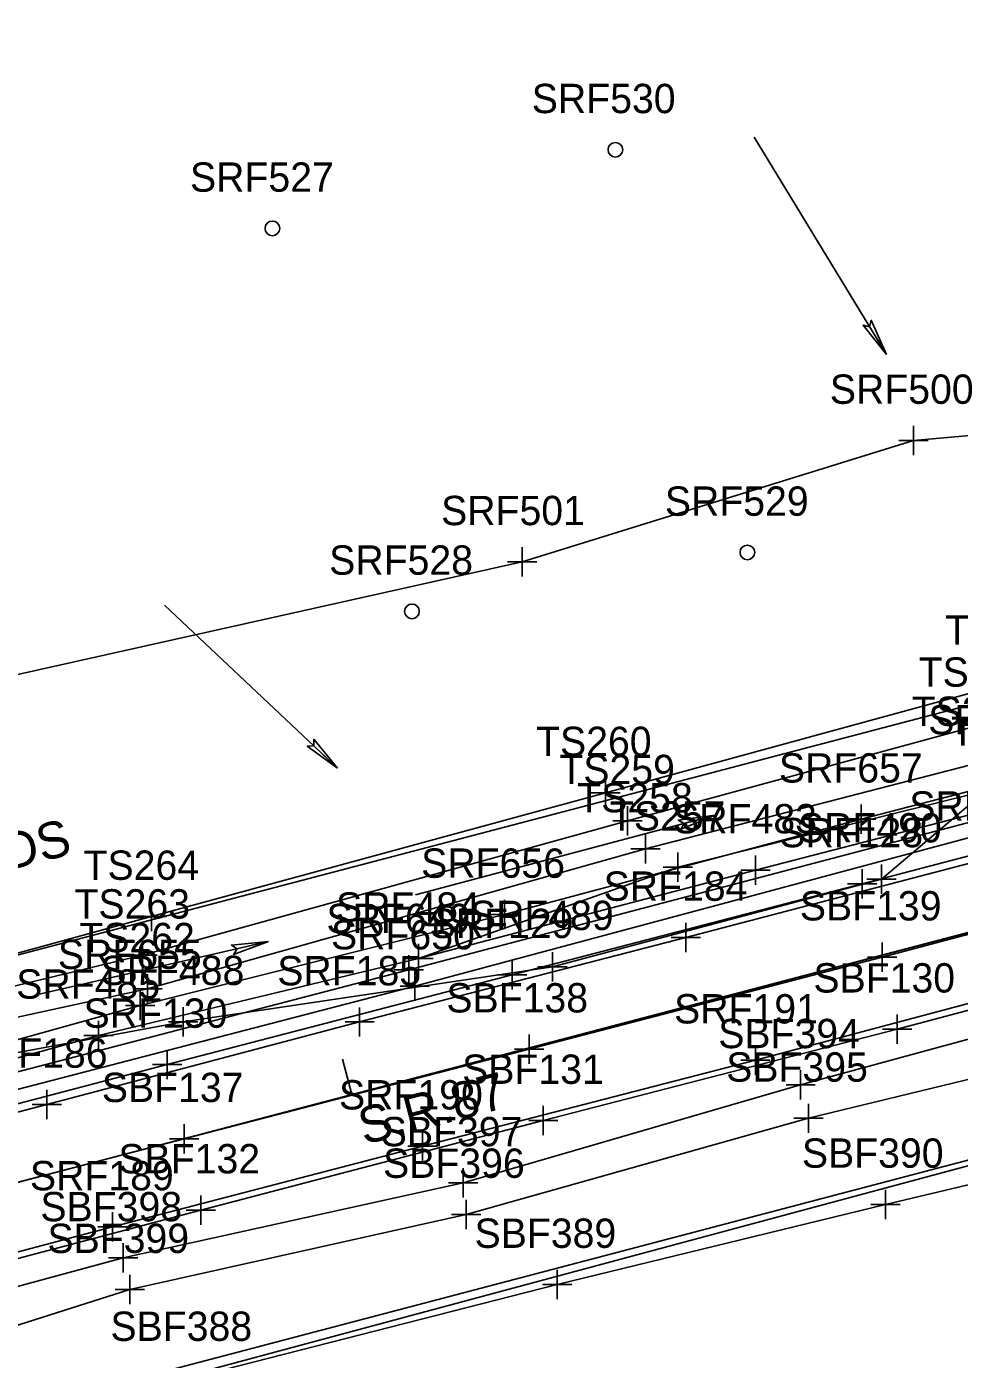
# Model space of a CAD drawing. Extents: x 818717 to 846077, y 440014 to 541392.
# Drawn here: x 831206.2 to 831333.4, y 492949.3 to 493131.1 of the extents above; entities that cross this region are included whole.
import ezdxf

# ---------------------------------------------------------------- set-up
doc = ezdxf.new("R2010")
doc.units = 0
for name, color, linetype in [('SURVEY - CENTERLINE - Preliminary', 7, 'Continuous'), ('SURVEY - CENTERLINE - Preliminary Text', 7, 'Continuous'), ('SURVEY - DRAINAGE - Area Shapes', 7, 'Continuous'), ('SURVEY - DRAINAGE - Natural Features Text', 7, 'Continuous'), ('SURVEY - DTM - Breaklines', 7, 'Continuous'), ('SURVEY - DTM - Breaklines - Points - Locators', 7, 'Continuous'), ('SURVEY - DTM - Breaklines - Points - Numbers', 7, 'Continuous'), ('SURVEY - DTM - Spot Points - Locators', 7, 'Continuous'), ('SURVEY - DTM - Spot Points - Point Numbers', 7, 'Continuous'), ('SURVEY - PROPERTY - ROW Lines', 7, 'Continuous'), ('SURVEY - TRAFFIC CONTROL - Pavement Marking - Points - Locators', 7, 'Continuous'), ('SURVEY - TRAFFIC CONTROL - Pavement Marking - Points - Numbers', 7, 'Continuous'), ('SURVEY - TRAFFIC CONTROL - Pavement Marking with Text', 7, 'Continuous'), ('SURVEY - TRANSPORTATION - Roads', 7, 'Continuous'), ('SURVEY - TRANSPORTATION - Roads - Points - Locators', 7, 'Continuous'), ('SURVEY - TRANSPORTATION - Roads - Points - Numbers', 7, 'Continuous'), ('SURVEY - TRANSPORTATION - Roads Text', 7, 'Continuous'), ('SURVEY - UTILITIES - Electric (Overhead) with Text', 7, 'Continuous'), ('SURVEY - UTILITIES - Telephone (Underground) - Points - Locators', 7, 'Continuous'), ('SURVEY - UTILITIES - Telephone (Underground) - Points - Numbers', 7, 'Continuous'), ('SURVEY - UTILITIES - Telephone (Underground) with Text', 7, 'Continuous'), ('SURVEY - UTILITIES - Water - Points - Locators', 7, 'Continuous'), ('SURVEY - UTILITIES - Water - Points - Numbers', 7, 'Continuous'), ('SURVEY - UTILITIES - Water with Text', 7, 'Continuous'), ('SURVEY - VEGETATION - Features - Points - Locators', 7, 'Continuous'), ('SURVEY - VEGETATION - Features - Points - Numbers', 7, 'Continuous'), ('SURVEY - VEGETATION - Features with Text', 7, 'Continuous')]:
    doc.layers.add(name, color=color, linetype=linetype)

msp = doc.modelspace()

# ---------------------------------------------------------------- linework, layer by layer
at = {"layer": 'SURVEY - CENTERLINE - Preliminary'}
msp.add_line((830960.37, 492909.24), (831419.96, 493029.94), dxfattribs=at)
msp.add_line((830960.37, 492909.24), (831419.96, 493029.94), dxfattribs=at)
msp.add_line((830960.37, 492909.24), (831419.96, 493029.94), dxfattribs=at)
at = {"layer": 'SURVEY - CENTERLINE - Preliminary Text'}
msp.add_line((831250.53, 492985.45), (831249.26, 492990.28), dxfattribs=at)
at = {"layer": 'SURVEY - DRAINAGE - Area Shapes'}
msp.add_lwpolyline([(833331.86, 493535.43), (832825.85, 493400.54), (832121.68, 493216.64), (831495.16, 493049.75), (830960.37, 492909.24), (830124.73, 492686.08), (830069.9, 493396.23), (830870.86, 494031.84), (831248.11, 494413.67), (831536.95, 494545.33), (832050.07, 494534.01), (832097.96, 494614.84), (832139.36, 494784.62), (832167.46, 494840.58), (832274.31, 494844.36), (832647.22, 494804.13), (832934.24, 494910.41), (833081.03, 494456.05), (833331.86, 493535.43)], dxfattribs=at)
at = {"layer": 'SURVEY - DRAINAGE - Natural Features Text'}
for p, q in [((831323.47, 493086.43), (831305.44, 493116.04)), ((831322.06, 493088.74), (831323.47, 493086.43)), ((831248.57, 493029.99), (831224.99, 493052.2)), ((831246.6, 493031.84), (831248.57, 493029.99)), ((831300.12, 493023.57), (831259.21, 493012.69)), ((831297.51, 493022.88), (831300.12, 493023.57)), ((831239.18, 493006.35), (831207.27, 492999.01)), ((831236.55, 493005.74), (831239.18, 493006.35))]:
    msp.add_line(p, q, dxfattribs=at)
for points in [[(831323.47, 493086.43), (831320.29, 493090.4), (831321.18, 493090.19), (831321.4, 493091.08)], [(831248.57, 493029.99), (831244.45, 493032.98), (831245.37, 493033.01), (831245.34, 493033.92)], [(831300.12, 493023.57), (831295.41, 493021.64), (831295.87, 493022.44), (831295.07, 493022.9)], [(831239.18, 493006.35), (831234.41, 493004.58), (831234.9, 493005.36), (831234.12, 493005.85)]]:
    msp.add_lwpolyline(points, close=True, dxfattribs=at)
for points in [[(831323.47, 493086.43), (831320.29, 493090.4), (831321.18, 493090.19), (831321.4, 493091.08), (831323.47, 493086.43)], [(831248.57, 493029.99), (831244.45, 493032.98), (831245.37, 493033.01), (831245.34, 493033.92), (831248.57, 493029.99)], [(831300.12, 493023.57), (831295.41, 493021.64), (831295.87, 493022.44), (831295.07, 493022.9), (831300.12, 493023.57)], [(831239.18, 493006.35), (831234.41, 493004.58), (831234.9, 493005.36), (831234.12, 493005.85), (831239.18, 493006.35)]]:
    msp.add_lwpolyline(points, dxfattribs=at)
at = {"layer": 'SURVEY - DTM - Breaklines'}
for points in [[(831172.33, 492965.05), (831181.59, 492967.43), (831227.67, 492979.44), (831274.72, 492991.66), (831322.92, 493004.21), (831368.33, 493016.26), (831413.81, 493028.29), (831465.87, 493041.9), (831511.63, 493053.91), (831556.79, 493065.9), (831604.84, 493079.03), (831650.91, 493091.16), (831699.1, 493103.99), (831742.48, 493115.71)], [(831532.14, 493094.44), (831486.29, 493082.49), (831415.63, 493063.89), (831383.16, 493053.36), (831340.91, 493041.84), (831285.15, 493026.64), (831223.23, 493009.75), (831163.61, 492993.48)], [(831533.39, 493093.08), (831489.03, 493078.67), (831431.59, 493059.14), (831388.21, 493049.94), (831337.17, 493036.1), (831288.16, 493022.81), (831221.99, 493004.47), (831163.9, 492990.46)], [(831535.36, 493091.17), (831488.68, 493075.37), (831432.58, 493055.29), (831391.04, 493045.72), (831336.22, 493030.75), (831290.63, 493018.96), (831222.65, 492999.88), (831164.87, 492987.27)], [(831537.69, 493087.97), (831489.3, 493071.65), (831438.65, 493053.39), (831396.75, 493041.74), (831341.58, 493028.03), (831295.03, 493016.46), (831259.62, 493004.04)], [(831550.6, 493086.08), (831528.73, 493075.33), (831482.27, 493062.41), (831435.51, 493050.33), (831391.53, 493037.77), (831349.43, 493027.4), (831305.62, 493016.09), (831259.62, 493004.04), (831215.99, 492993.54), (831167.49, 492980.12)], [(831371.1, 493001.48), (831357.72, 492999.27), (831311.78, 492986.79), (831265.73, 492973.41), (831219.33, 492963.18), (831175.85, 492951.43)], [(831358.62, 492993.34), (831312.86, 492982.22), (831266.15, 492969.1), (831220.27, 492958.85), (831177.33, 492945.24)], [(831183.26, 492932.89), (831228.9, 492946.86), (831278.55, 492959.55), (831323.37, 492970.48), (831362.8, 492979.81)]]:
    msp.add_lwpolyline(points, dxfattribs=at)
at = {"layer": 'SURVEY - DTM - Breaklines - Points - Locators'}
for p, q in [((831285.15, 493028.64), (831285.15, 493024.64)), ((831287.15, 493026.64), (831283.15, 493026.64)), ((831288.16, 493024.81), (831288.16, 493020.81)), ((831290.16, 493022.81), (831286.16, 493022.81)), ((831290.63, 493020.96), (831290.63, 493016.96)), ((831292.63, 493018.96), (831288.63, 493018.96)), ((831295.03, 493018.46), (831295.03, 493014.46)), ((831305.62, 493018.09), (831305.62, 493014.09)), ((831297.03, 493016.46), (831293.03, 493016.46)), ((831307.62, 493016.09), (831303.62, 493016.09)), ((831223.23, 493011.75), (831223.23, 493007.75)), ((831225.23, 493009.75), (831221.23, 493009.75)), ((831221.99, 493006.47), (831221.99, 493002.47)), ((831259.62, 493006.04), (831259.62, 493002.04)), ((831322.92, 493006.21), (831322.92, 493002.21)), ((831223.99, 493004.47), (831219.99, 493004.47)), ((831261.62, 493004.04), (831257.62, 493004.04)), ((831324.92, 493004.21), (831320.92, 493004.21)), ((831222.65, 493001.88), (831222.65, 492997.88)), ((831224.65, 492999.88), (831220.65, 492999.88)), ((831215.99, 492995.54), (831215.99, 492991.54)), ((831217.99, 492993.54), (831213.99, 492993.54)), ((831274.72, 492993.66), (831274.72, 492989.66)), ((831276.72, 492991.66), (831272.72, 492991.66)), ((831311.78, 492988.79), (831311.78, 492984.79)), ((831313.78, 492986.79), (831309.78, 492986.79)), ((831312.86, 492984.22), (831312.86, 492980.22)), ((831314.86, 492982.22), (831310.86, 492982.22)), ((831227.67, 492981.44), (831227.67, 492977.44)), ((831229.67, 492979.44), (831225.67, 492979.44)), ((831265.73, 492975.41), (831265.73, 492971.41)), ((831267.73, 492973.41), (831263.73, 492973.41)), ((831323.37, 492972.48), (831323.37, 492968.48)), ((831266.15, 492971.1), (831266.15, 492967.1)), ((831268.15, 492969.1), (831264.15, 492969.1)), ((831325.37, 492970.48), (831321.37, 492970.48)), ((831219.33, 492965.18), (831219.33, 492961.18)), ((831221.33, 492963.18), (831217.33, 492963.18)), ((831278.55, 492961.55), (831278.55, 492957.55)), ((831220.27, 492960.85), (831220.27, 492956.85)), ((831222.27, 492958.85), (831218.27, 492958.85)), ((831280.55, 492959.55), (831276.55, 492959.55))]:
    msp.add_line(p, q, dxfattribs=at)
at = {"layer": 'SURVEY - DTM - Spot Points - Locators'}
for centre in [(831286.5, 493114.33), (831239.7, 493103.61), (831304.51, 493059.41), (831258.74, 493051.37)]:
    msp.add_circle(centre, 1, dxfattribs=at)
at = {"layer": 'SURVEY - PROPERTY - ROW Lines'}
for p, q in [((831412.34, 493058.96), (830952.75, 492938.26)), ((830967.99, 492880.22), (831427.58, 493000.93))]:
    msp.add_line(p, q, dxfattribs=at)
at = {"layer": 'SURVEY - TRAFFIC CONTROL - Pavement Marking - Points - Locators'}
for p, q in [((831296.13, 493008.89), (831296.13, 493004.89)), ((831298.13, 493006.89), (831294.13, 493006.89)), ((831251.61, 492997.36), (831251.61, 492993.36)), ((831253.61, 492995.36), (831249.61, 492995.36)), ((831305.6, 492992.16), (831305.6, 492988.16)), ((831307.6, 492990.16), (831303.6, 492990.16)), ((831208.94, 492986.12), (831208.94, 492982.12)), ((831210.94, 492984.12), (831206.94, 492984.12)), ((831260.2, 492980.43), (831260.2, 492976.43)), ((831262.2, 492978.43), (831258.2, 492978.43)), ((831217.88, 492969.4), (831217.88, 492965.4)), ((831219.88, 492967.4), (831215.88, 492967.4))]:
    msp.add_line(p, q, dxfattribs=at)
at = {"layer": 'SURVEY - TRAFFIC CONTROL - Pavement Marking with Text'}
for points in [[(832159.39, 493235.77), (832116.7, 493224.52), (832072.63, 493213.17), (832030, 493201.97), (831987.46, 493190.83), (831936.58, 493177.36), (831894.1, 493165.96), (831849.46, 493153.92), (831808.03, 493142.52), (831768.36, 493131.66), (831727.87, 493120.89), (831684.5, 493109.18), (831641.68, 493097.86), (831599.16, 493086.58), (831554.58, 493074.61), (831511.86, 493063.5), (831467.07, 493051.66), (831425.05, 493040.69), (831380.34, 493029.11), (831337.84, 493017.82), (831296.13, 493006.89), (831251.61, 492995.36), (831208.94, 492984.12), (831169.87, 492973.88)], [(831174.64, 492955.97), (831217.88, 492967.4), (831260.2, 492978.43), (831305.6, 492990.16), (831350.87, 493002.2), (831397.34, 493014.25), (831441.59, 493025.83), (831487.77, 493037.91), (831534.41, 493050.33), (831587.19, 493064.38), (831630.52, 493075.92), (831676.82, 493088.3), (831723.86, 493100.96), (831758.43, 493110.25), (831806.28, 493123.18), (831848.98, 493134.67), (831896.65, 493147.52), (831940.52, 493159.26), (831989.17, 493172.11), (832037.06, 493184.69), (832086.82, 493197.77), (832134.83, 493210.3)]]:
    msp.add_lwpolyline(points, dxfattribs=at)
at = {"layer": 'SURVEY - TRANSPORTATION - Roads'}
for points in [[(831740.14, 493125.18), (831693.82, 493112.89), (831648.31, 493100.78), (831602.5, 493088.65), (831573.14, 493081.02), (831536.49, 493071.33), (831509.09, 493063.99), (831462.95, 493051.69), (831417.27, 493039.63), (831365.78, 493026.17), (831320.15, 493014.2), (831272.42, 493001.81), (831225.35, 492989.57), (831179.26, 492977.48), (831169.53, 492974.82)], [(831745.28, 493105.9), (831698.71, 493093.56), (831652.79, 493081.06), (831606.96, 493068.69), (831560.39, 493056.4), (831514.16, 493044.16), (831468.16, 493032.15), (831422.28, 493020.03), (831370.82, 493006.55), (831324.94, 492994.38), (831276.67, 492981.92), (831229.94, 492969.71), (831184.11, 492957.61), (831175.07, 492955.18)]]:
    msp.add_lwpolyline(points, dxfattribs=at)
at = {"layer": 'SURVEY - TRANSPORTATION - Roads - Points - Locators'}
for p, q in [((831320.15, 493016.2), (831320.15, 493012.2)), ((831322.15, 493014.2), (831318.15, 493014.2)), ((831272.42, 493003.81), (831272.42, 492999.81)), ((831274.42, 493001.81), (831270.42, 493001.81)), ((831324.94, 492996.38), (831324.94, 492992.38)), ((831326.94, 492994.38), (831322.94, 492994.38)), ((831225.35, 492991.57), (831225.35, 492987.57)), ((831227.35, 492989.57), (831223.35, 492989.57)), ((831276.67, 492983.92), (831276.67, 492979.92)), ((831278.67, 492981.92), (831274.67, 492981.92)), ((831229.94, 492971.71), (831229.94, 492967.71)), ((831231.94, 492969.71), (831227.94, 492969.71))]:
    msp.add_line(p, q, dxfattribs=at)
at = {"layer": 'SURVEY - UTILITIES - Electric (Overhead) with Text'}
msp.add_lwpolyline([(832667.18, 493331.74), (832415.28, 493266.23), (832147.85, 493195.27), (831907.96, 493131.64), (831666.03, 493064.14), (831375.19, 492986.65), (831101.3, 492913.04)], dxfattribs=at)
at = {"layer": 'SURVEY - UTILITIES - Telephone (Underground) - Points - Locators'}
for p, q in [((831258.34, 493004.49), (831258.34, 493000.49)), ((831260.34, 493002.49), (831256.34, 493002.49)), ((831259.12, 493002.26), (831259.12, 492998.26)), ((831261.12, 493000.26), (831257.12, 493000.26))]:
    msp.add_line(p, q, dxfattribs=at)
at = {"layer": 'SURVEY - UTILITIES - Telephone (Underground) with Text'}
for points in [[(831168.45, 492979.07), (831258.34, 493002.49), (831351.65, 493027.04)], [(831169.15, 492976.87), (831259.12, 493000.26), (831352.34, 493025.2)]]:
    msp.add_lwpolyline(points, dxfattribs=at)
at = {"layer": 'SURVEY - UTILITIES - Water - Points - Locators'}
for p, q in [((831320.05, 493025.02), (831320.05, 493021.02)), ((831322.05, 493023.02), (831318.05, 493023.02)), ((831271.35, 493012.03), (831271.35, 493008.03)), ((831273.35, 493010.03), (831269.35, 493010.03)), ((831221.68, 492999.59), (831221.68, 492995.59)), ((831223.68, 492997.59), (831219.68, 492997.59))]:
    msp.add_line(p, q, dxfattribs=at)
at = {"layer": 'SURVEY - UTILITIES - Water with Text'}
msp.add_lwpolyline([(831168.53, 492982.83), (831221.68, 492997.59), (831271.35, 493010.03), (831320.05, 493023.02), (831382.11, 493039.09), (831464.43, 493059.02), (831521.6, 493075.98), (831637.27, 493105.47), (831699.54, 493130.69), (831734.63, 493142.29), (831763.92, 493149.4), (831800.53, 493157.83), (831844.47, 493169.57), (831878.73, 493177.18), (831933.72, 493193.59), (832000.95, 493211.25), (832058.59, 493225.48), (832113.6, 493238.29), (832172.68, 493261.93), (832217.98, 493273.66), (832269.17, 493287.2), (832330.79, 493299.45)], dxfattribs=at)
at = {"layer": 'SURVEY - VEGETATION - Features - Points - Locators'}
for p, q in [((831327.18, 493076.68), (831327.18, 493072.68)), ((831329.18, 493074.68), (831325.18, 493074.68)), ((831273.8, 493060.13), (831273.8, 493056.13)), ((831275.8, 493058.13), (831271.8, 493058.13)), ((831322.83, 493016.85), (831322.83, 493012.85)), ((831324.83, 493014.85), (831320.83, 493014.85)), ((831277.91, 493004.9), (831277.91, 493000.9)), ((831279.91, 493002.9), (831275.91, 493002.9)), ((831227.54, 492997.4), (831227.54, 492993.4)), ((831229.54, 492995.4), (831225.54, 492995.4))]:
    msp.add_line(p, q, dxfattribs=at)
at = {"layer": 'SURVEY - VEGETATION - Features with Text'}
msp.add_lwpolyline([(831133.17, 493025.25), (831188.61, 493039.11), (831273.8, 493058.13), (831327.18, 493074.68), (831372.45, 493078.69), (831446.52, 493103.4), (831511.7, 493128.91), (831543.94, 493118.92), (831551.05, 493086.4), (831538.72, 493077.69), (831488.18, 493059.71), (831414.15, 493041.53), (831340.28, 493029.6), (831322.83, 493014.85), (831277.91, 493002.9), (831227.54, 492995.4), (831165.97, 492983.97)], dxfattribs=at)

# ---------------------------------------------------------------- texts
at = {"layer": 'SURVEY - DTM - Breaklines - Points - Numbers'}
for s, p in [('TS256', (831331.51, 493046.84)), ('TS255', (831327.88, 493041.1)), ('TS254', (831326.93, 493035.75)), ('TS253', (831332.29, 493033.03)), ('TS260', (831275.68, 493031.64)), ('TS259', (831278.86, 493027.81)), ('TS258', (831281.3, 493023.96)), ('TS257', (831285.75, 493021.46)), ('SRF483', (831294.38, 493021.09)), ('TS264', (831213.94, 493014.75)), ('TS263', (831212.7, 493009.47)), ('SRF484', (831248.38, 493009.04)), ('SBF139', (831311.67, 493009.21)), ('TS262', (831213.36, 493004.88)), ('SRF485', (831204.75, 492998.54)), ('SBF138', (831263.44, 492996.66)), ('SBF394', (831300.54, 492991.79)), ('SBF395', (831301.62, 492987.22)), ('SBF137', (831216.43, 492984.44)), ('SBF397', (831254.49, 492978.41)), ('SBF396', (831254.8, 492974.1)), ('SBF390', (831311.95, 492975.48)), ('SBF398', (831208.05, 492968.18)), ('SBF399', (831209.01, 492963.85)), ('SBF389', (831267.29, 492964.55)), ('SBF388', (831217.61, 492951.86))]:
    msp.add_text(s, height=4, dxfattribs=at).set_placement(p)
at = {"layer": 'SURVEY - DTM - Spot Points - Point Numbers'}
for s, p in [('SRF530', (831275.09, 493119.33)), ('SRF527', (831228.46, 493108.61)), ('SRF529', (831293.25, 493064.41)), ('SRF528', (831247.45, 493056.37))]:
    msp.add_text(s, height=4, dxfattribs=at).set_placement(p)
at = {"layer": 'SURVEY - TRAFFIC CONTROL - Pavement Marking - Points - Numbers'}
for s, p in [('SRF183', (831326.6, 493022.82)), ('SRF184', (831284.89, 493011.89)), ('SRF185', (831240.37, 493000.36)), ('SRF191', (831294.51, 492995.16)), ('SRF186', (831197.59, 492989.12)), ('SRF190', (831248.79, 492983.43)), ('SRF189', (831206.62, 492972.4))]:
    msp.add_text(s, height=4, dxfattribs=at).set_placement(p)
at = {"layer": 'SURVEY - TRANSPORTATION - Roads - Points - Numbers'}
for s, p in [('SRF128', (831308.86, 493019.2)), ('SRF129', (831261.16, 493006.81)), ('SBF130', (831313.52, 492999.38)), ('SRF130', (831213.94, 492994.57)), ('SBF131', (831265.59, 492986.92)), ('SBF132', (831218.7, 492974.71))]:
    msp.add_text(s, height=4, dxfattribs=at).set_placement(p)
at = {"layer": 'SURVEY - TRANSPORTATION - Roads Text'}
msp.add_text('S.R.87', height=5, rotation=14.7154, dxfattribs=at).set_placement((831252.22, 492978.59))
at = {"layer": 'SURVEY - UTILITIES - Telephone (Underground) - Points - Numbers'}
for s, p in [('SRF649', (831247.08, 493007.49)), ('SRF650', (831247.7, 493005.26))]:
    msp.add_text(s, height=4, dxfattribs=at).set_placement(p)
at = {"layer": 'SURVEY - UTILITIES - Water - Points - Numbers'}
for s, p in [('SRF657', (831308.81, 493028.02)), ('SRF656', (831260, 493015.03)), ('SRF655', (831210.44, 493002.59))]:
    msp.add_text(s, height=4, dxfattribs=at).set_placement(p)
at = {"layer": 'SURVEY - VEGETATION - Features - Points - Numbers'}
for s, p in [('SRF500', (831315.76, 493079.68)), ('SRF501', (831262.72, 493063.13)), ('SRF491', (831329.19, 493034.6)), ('SRF490', (831311.41, 493019.85)), ('SRF489', (831266.65, 493007.9)), ('SRF488', (831216.25, 493000.4))]:
    msp.add_text(s, height=4, dxfattribs=at).set_placement(p)
at = {"layer": 'SURVEY - VEGETATION - Features with Text'}
msp.add_text('WOODS', height=5, rotation=14.7154, dxfattribs=at).set_placement((831187.42, 493011.72))

doc.saveas('drawing.dxf')
